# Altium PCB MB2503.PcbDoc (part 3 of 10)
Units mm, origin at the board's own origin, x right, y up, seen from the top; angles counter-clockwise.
Board outline 127 x 97 mm, 6 copper layers (Top Layer, Signal Layer 1, Signal Layer 2, Signal Layer 3, Signal Layer 4, Bottom Layer), stack 1.557 mm thick; 572 components, 468 nets, 2377 pads, 1704 vias.
Unrouted connection lines stored in the file: 3.
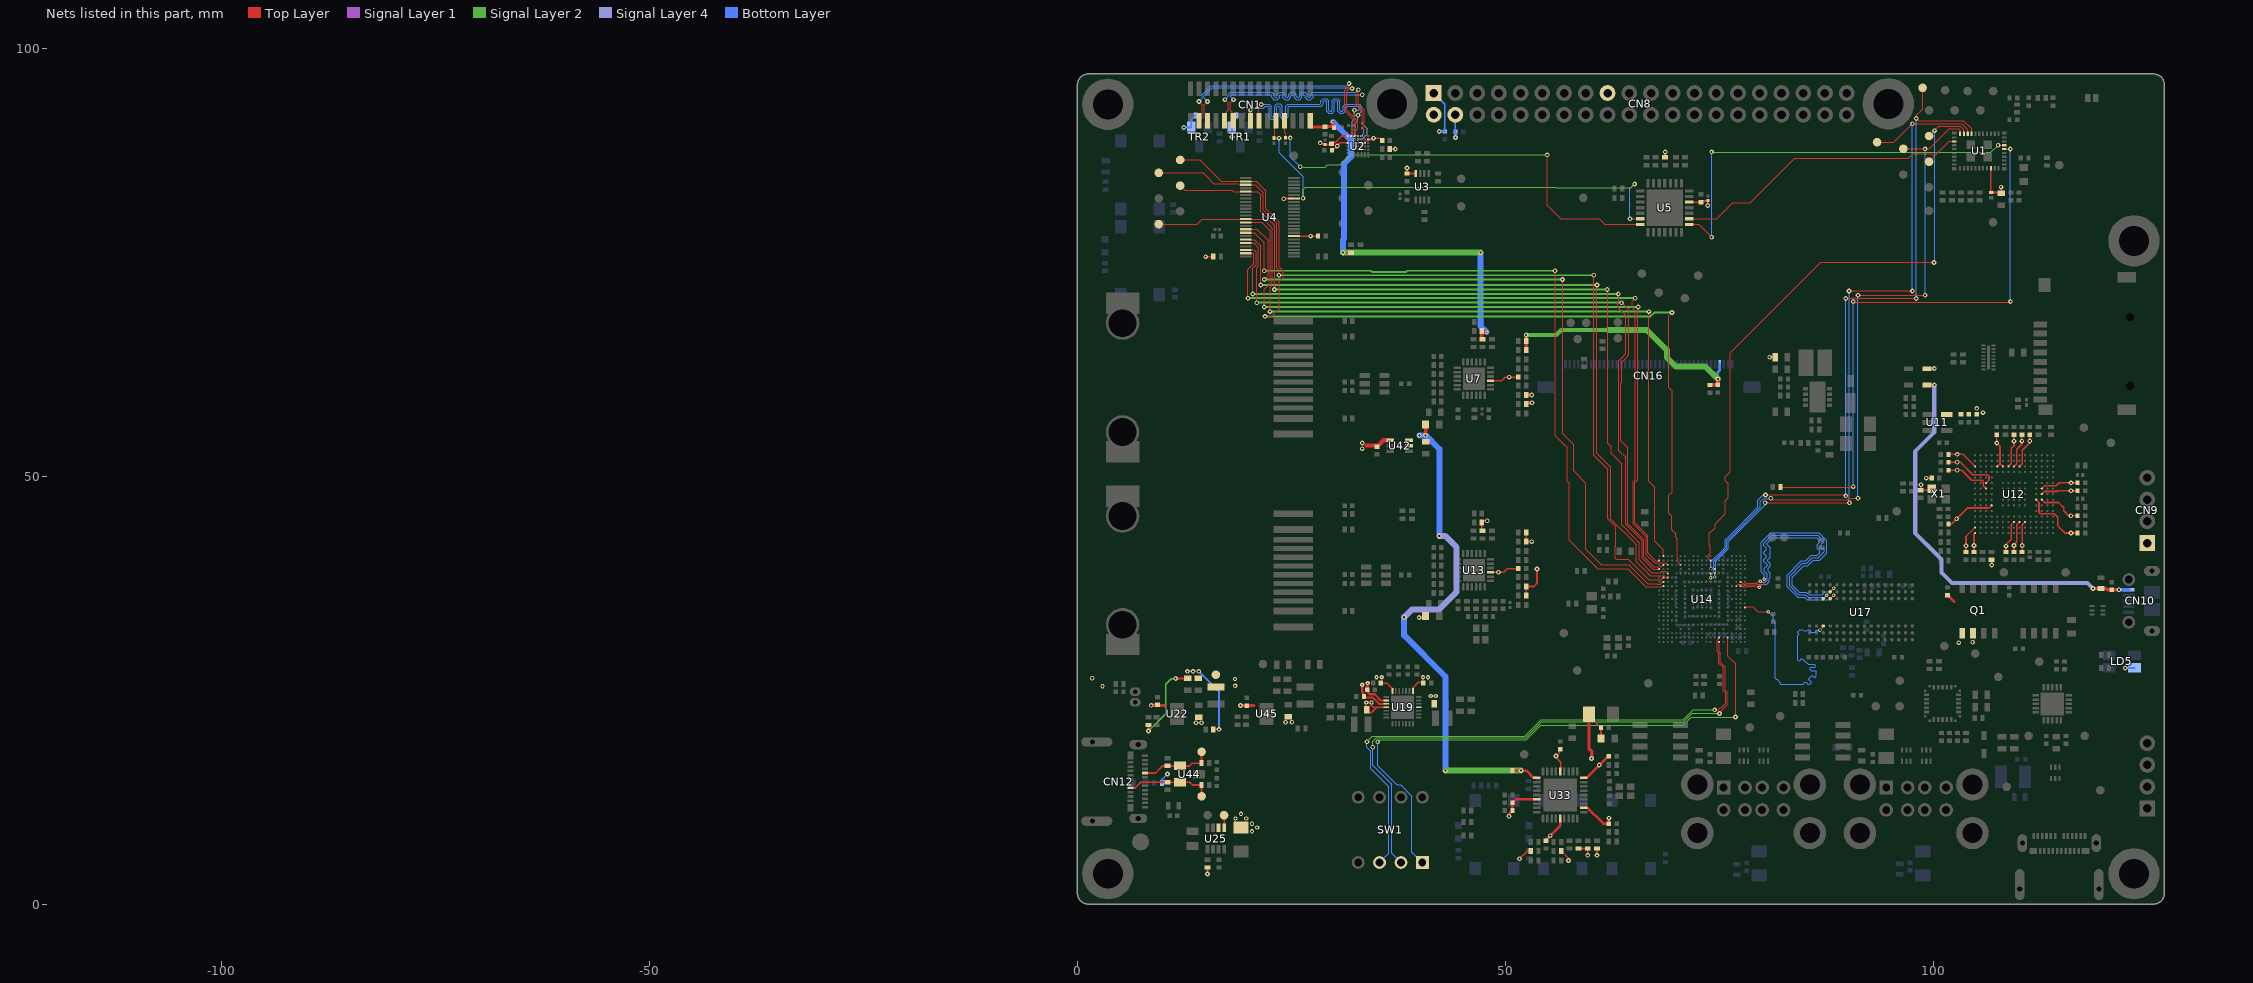
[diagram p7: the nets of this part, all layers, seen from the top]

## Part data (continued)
CN9 CN13: library part MCD-00029, "Header, 4x1, 2.54mm, VR, TH, T=5.84mm/2.54mm", Manufacturer=SAMTEC, Manufacturer_Part_Number=TSW-104-07-G-S
CN10: library part MCD-00028, "MicroUSB_TypeB, 5pins, 0.65mm, RA, SMD, T=2.9mm", Manufacturer=MOLEX, Manufacturer_Part_Number=1050170001
CN11: library part MCD-00655, "Header, 2x1, 1.25mm, VR, TH, T=2.25mm/2.3mm", Manufacturer=MOLEX, Manufacturer_Part_Number=53047-0210
CN16: library part MCD-02589, "Socket_FFC/FPC, 40pins, 0.5mm, RA, SMD, T=1.9mm", Manufacturer=MOLEX
D1 D3 D4: library part MCD-00034, Manufacturer=STMICROELECTRONICS, Manufacturer_HQ_COO=EU, Package=SOD-323
D2: library part MCD-00033, "Low Drop power Schottky rectifier(1A, 40V, 0.4V)", Manufacturer=STMICROELECTRONICS, Manufacturer_HQ_COO=EU, Package=DO216-AA
HW2: library part MCD-00235, "Sticker Board 25x9 mm", Manufacturer=N/A
HW3: library part MCD-00547, "Sticker product 25x9 mm", Manufacturer=N/A, Manufacturer_HQ_COO=Unknown
L1: library part MCD-00657, "Inductor, 2.4nH, +/-0.2nH, Itemp=850mA, 50R, 0402, T=0.6mm, Qmin=20", Manufacturer=MURATA, Manufacturer_Part_Number=LQW15AN2N4C00#, Package=0402
L2: library part MCD-00659, "Inductor, 2.2uH, +/-20%, 1050mA, 0R2, 0603, T=1mm", Manufacturer=MURATA, Manufacturer_Part_Number=LQM18PN2R2MGH, Package=0603
L3: library part MCD-00048, "Inductor, 4.7uH, +/-30%, 1A, 180mR, 1210, T=1.7mm", Manufacturer=MURATA, Manufacturer_Part_Number=LQH32PN4R7NN0L, Package=1210
L4 L5: library part MCD-00047, "Ferrite bead, 600R @1 00MHz, +/-25%, 350mA, 0R5, 0603, T=0.8mm", Manufacturer=TAI-TECH, Manufacturer_Part_Number=FCM1608KF-601T03, Package=0603
L6 L8: library part MCD-00161, "Inductor, 2.2uH, +/-20%, 2,2A, 84mR, 1008, T=1.2mm", Manufacturer=TOKO, Manufacturer_Part_Number=DFE252012P-2R2M{}P2, Package=1008
L9 L11: library part MCD-04058, "Inductor, 1uH, +/-20%, 3.6A, 57mR, 0806, T=1mm", Manufacturer="SAMSUNG ELECTRO-MECHANICS", Manufacturer_Part_Number=CIGT201610LH1R0MNE, Package=0806
L12: library part MCD-00305, "Ferrite bead, 26R @ 100Mhz, +/-25%, 6000mA, 0R007, 0603, T=0.75mm", Manufacturer=MURATA, Manufacturer_Part_Number=BLM18KG260TN1, Package=0603
LD1: library part MCD-00050, "LED, Green, 2V, 20mA, 0603", Manufacturer=EVERLIGHT, Manufacturer_Part_Number=19-213SYGC/S530-E2/TR8, Package=0603
LD2 LD4: library part MCD-00049, "LED, Red, 0603", Manufacturer=EVERLIGHT, Manufacturer_Part_Number=19-213/R6C-AP1Q2B/3T, Package=0603
LD3: library part MCD-01131, "LED Blue, 0603 SMD, Forward Voltage Min=2,8V, Max=3,1V", Manufacturer=EVERLIGHT, Manufacturer_Part_Number=19-217/BHC-ZL1M2RY/3T, Package=0603
LD5: library part MCD-02629, "LED Bicolor, Green, Red, 4-PLCC", Manufacturer="VISUAL COMMUNICATIONS COMPANY", Manufacturer_Part_Number=CMD6722VRVGCTR8, Package=4-PLCC
LD6: library part MCD-00321, "LED, Orange, 0603", Manufacturer=EVERLIGHT, Manufacturer_Part_Number=19-217/S2C-AM2N2VY/3T, Package=0603
LD7: library part MCD-00050, "LED, Green, 0603", Manufacturer=EVERLIGHT, Manufacturer_Part_Number=19-213SYGC/S530-E2/TR8, Package=0603
Q1 Q2: library part MCD-02152, "MOSFET, Dual N-channel 30 V, 0.016 Ω typ., 40 A, STripFET™ H5 Power MOSFET", Manufacturer=STMICROELECTRONICS, Manufacturer_HQ_COO=EU, Package=PowerFLAT-8
R1 R2 R10 R11 R12 R19 R20 R21 R28 R30 R45 R54 R55 R56 R57 R60 R61 R64 R68 R77 R81 R85 R88 R90 R91 R96 R103 R104 R105 R106 R133 R166 R167 R188 R189 R190 R191 R192: library part MCD-00052, "Resistor, 0R, 0402, +/-5%, 1/16W", Manufacturer=YAGEO, Manufacturer_Part_Number=RC0402JR-070RL, Package=0402
R3 R4 R5 R6 R7 R8 R9 R22 R23 R24 R25 R26 R29 R32 R33 R34 R38 R43 R48 R65 R69 R70 R72 R73 R78 R83 R84 R93 R100 R102 R141 R162 R163 R176 R178 R180 R187: library part MCD-00053, "Resistor, 10K, 0402, +/-1%, 1/16W", Manufacturer=YAGEO, Manufacturer_Part_Number=RC0402FR-0710KL, Package=0402
R13 R53 R58 R59 R87 R89 R94: library part MCD-00065, "Resistor, 4K7, 0402, +/-1%, 1/16W", Manufacturer=YAGEO, Manufacturer_Part_Number=RC0402FR-074K7L, Package=0402
R14 R15 R16 R17 R18 R144 R149: library part MCD-00063, "Resistor, 47K, 0402, +/-1%, 1/16W", Manufacturer=YAGEO, Manufacturer_Part_Number=RC0402FR-0747KL, Package=0402
R27 R52 R76 R110: library part MCD-00441, "Resistor, 270R, 0402, +/-1%, 1/16W", Manufacturer=YAGEO, Manufacturer_Part_Number=RC0402FR-07270RL, Package=0402
R31 R71 R75 R80 R82 R108 R120 R121 R168 R169: library part MCD-00068, "Resistor, 1K5, 0402, +/-1%, 1/16W", Manufacturer=YAGEO, Manufacturer_Part_Number=RC0402FR-071K5L, Package=0402
R35 R115 R116: library part MCD-00181, "Resistor, 0R, 0603, +/- 0.5mR, 1/4W", Manufacturer="ROHM SEMICONDUCTOR", Manufacturer_Part_Number=PMR03EZPJ000, Package=0603
R36 R41 R51 R79 R86 R98 R109: library part MCD-00455, "Resistor, 33R, 0402, +/-1%, 1/16W", Manufacturer=YAGEO, Manufacturer_Part_Number=RC0402FR-0733RL, Package=0402
R37 R39 R40 R42 R92 R95 R97 R99: library part MCD-00565, "Resistor, 49R9, 0402, +/-1%, 1/16W", Manufacturer=YAGEO, Manufacturer_Part_Number=RC0402FR-0749R9L, Package=0402
R44 R46 R156 R158 R159 R160 R161 R164 R165: library part MCD-00059, "Resistor, 100K, 0402, +/-1%, 1/16W", Manufacturer=YAGEO, Manufacturer_Part_Number=RC0402FR-07100KL, Package=0402
R47 R101: library part MCD-00723, "Resistor, 12K1, 0402, +/-1%, 1/16W", Manufacturer=YAGEO, Manufacturer_Part_Number=RC0402FR-0712K1L, Package=0402
R49: library part MCD-00060, "Resistor, 10R, 0603, +/-1%, 1/4W", Manufacturer="ROHM SEMICONDUCTOR", Manufacturer_Part_Number=ESR03EZPF10R0, Package=0603
R50 R107: library part MCD-00189, "Resistor, 22R, 0402, +/-1%, 1/16W", Manufacturer=YAGEO, Manufacturer_Part_Number=RC0402FR-0722RL, Package=0402
R62 R63: library part MCD-00433, "Resistor, 2K4, 0402, +/-1%, 1/16W", Manufacturer=YAGEO, Manufacturer_Part_Number=RC0402FR-072K4L, Package=0402
R66 R128: library part MCD-00185, "Resistor, 3K, 0402, +/-1%, 1/16W", Manufacturer=YAGEO, Manufacturer_Part_Number=RC0402FR-073KL, Package=0402
R67 R186: library part MCD-00489, "Resistor, 560R, 0402, +/-1%, 1/16W", Manufacturer=YAGEO, Manufacturer_Part_Number=RC0402FR-07560RL, Package=0402
R74 R173 R175 R177 R182: library part MCD-00067, "Resistor, 100R, 0402, +/- 1%, 1/16W", Manufacturer=YAGEO, Manufacturer_Part_Number=RC0402FR-07100RL, Package=0402
R111: library part MCD-03129, "Resistor, 12mR, 0603, +/-1%, 1/2W", Manufacturer=VISHAY, Manufacturer_Part_Number=WFCP0603R0120FE66, Package=0603
R112 R179: library part MCD-00120, "Resistor, 240R, 0402, +/-1%, 1/16W", Manufacturer=YAGEO, Manufacturer_Part_Number=RC0402FR-07240RL, Package=0402
R113: library part MCD-00165, "Resistor, 150K, 0402, +/-1%, 1/16W", Manufacturer=YAGEO, Manufacturer_Part_Number=RC0402FR-07150KL, Package=0402
R114: library part MCD-00166, "Resistor, 120K, 0402, +/-1%, 1/16W", Manufacturer=YAGEO, Manufacturer_Part_Number=RC0402FR-07120KL, Package=0402
R117 R125 R152 R183: library part MCD-00062, "Resistor, 330R, 0402, +/-1%, 1/16W", Manufacturer=YAGEO, Manufacturer_Part_Number=RC0402FR-07330RL, Package=0402
R129: library part MCD-00384, "Resistor, 13K, 0603,+/-1%, 1/10W", Manufacturer=YAGEO, Manufacturer_Part_Number=RC0603FR-0713KL, Package=0603
R134: library part MCD-00420, "Resistor, 2K ,0603, +/-1%, 1/10W", Manufacturer=YAGEO, Manufacturer_Part_Number=RC0603FR-072KL, Package=0603
R135: library part MCD-00521, "Resistor, 75K, 0402, +/-1%, 1/16W", Manufacturer=YAGEO, Manufacturer_Part_Number=RC0402FR-0775KL, Package=0402
R136: library part MCD-00435, "Resistor, 24K, 0402, +/-1%, 1/16W", Manufacturer=YAGEO, Manufacturer_Part_Number=RC0402FR-0724KL, Package=0402
R142: library part MCD-00259, "Resistor, 33K, 0603, +/-1%, 1/10W", Manufacturer=YAGEO, Manufacturer_Part_Number=RC0603FR-0733KL, Package=0603
R143: library part MCD-00530, "Resistor, 8K2, 0603, +/-1%, 1/10W", Manufacturer=YAGEO, Manufacturer_Part_Number=RC0603FR-078K2L, Package=0603
R145 R147: library part MCD-00333, "Resistor, 5K1, 0402, +/-1%, 1/16W", Manufacturer=YAGEO, Manufacturer_Part_Number=RC0402FR-075K1L, Package=0402
R146: library part MCD-00187, "Resistor, 12K, 0402, +/-1%, 1/16W", Manufacturer=YAGEO, Manufacturer_Part_Number=RC0402FR-0712KL, Package=0402
R153 R154 R155 R157 R170 R171 R174 R181 R198 R200 R207 R209 R214 R215: library part MCD-00061, "Resistor, 1K, 0402, +/-1%,1/16W", Manufacturer=YAGEO, Manufacturer_Part_Number=RC0402FR-071KL, Package=0402
R172 R184: library part MCD-00507, "Resistor, 680R, 0402, +/-1%, 1/16W", Manufacturer=YAGEO, Manufacturer_Part_Number=RC0402FR-07680RL, Package=0402
R185: library part MCD-00481, "Resistor, 47R, 0402, +/-1%, 1/16W", Manufacturer=YAGEO, Manufacturer_Part_Number=RC0402FR-0747RL, Package=0402
SW1: library part MCD-02256, "Quad SPST switch, TH, 2.54mm pitch, height 7.5mm", Manufacturer=ECE, Package=9.65x12.2mm
TP1 TP2 TP3 TP4 TP5 TP6 TP7 TP8 TP9 TP10 TP11 TP12 TP13 TP14 TP15 TP16 TP17 TP18 TP19 TP20 TP21 TP22 TP23 TP24 TP25 TP26 TP27 TP28 TP29 TP30 TP31 TP32 TP33 TP34 TP35 TP36 TP37 TP38 TP39 TP40 TP41 TP42 TP43 TP44 TP45 TP46 TP47 TP48 TP50 TP51 TP52 TP53 TP54 TP55 TP56 TP57 TP58 TP59 TP61 TP63 TP64 TP65 TP74 TP75: library part MCD-00074, "Test Point 1mm", Manufacturer=N/A, Manufacturer_HQ_COO=Unknown
TP49 TP62 TP67 TP68 TP73 TP77: library part MCD-00074, "Test Point, SMD, 1mm", Manufacturer=N/A, Manufacturer_HQ_COO=Unknown
TP76: library part MCD-00177, "Test Point, SMD, 2mm", Manufacturer=N/A
TR1 TR2: library part MCD-02156, "MOSFET, N-Channel , Vds: 25V, Id: 0,22A, Vgs(th): 1.06V, Vgs(max): +/-8V, Rdson:5ohm@Vgs=2.7V, Qg=0,49nC", Manufacturer="ON SEMICONDUCTOR", Manufacturer_Part_Number=FDV301N, Package=SOT23-3
U1: library part MCD-00268, "IEEE802.11b/g/n W-LAN + Bluetooth 4.1+EDR module", Manufacturer=MURATA, Manufacturer_Part_Number=LBEE5KL1DX-977, Package=6.95x5.15x1.1mm
U2: library part MCD-02213, "Dual mode MIPI CSI-2 / SMIA CCP2 de-serializer", Manufacturer=STMICROELECTRONICS, Manufacturer_HQ_COO=EU, Manufacturer_Part_Number=STMIPID02/TR, Package=VFBGA-49
U3: library part MCD-00264, "Dual bit dual supply bus transceiver", Manufacturer="TEXAS INSTRUMENTS", Package=VSSOP-8
U4: library part MCD-02226, "16-bit translating transceiver", Manufacturer="TEXAS INSTRUMENTS", Package=TVSOP-56
U5: library part MCD-02210, "16-bit port expander with I2C control", Manufacturer=MICROCHIP, Manufacturer_Part_Number=MCP23017T-E/ML, Package=QFN-28
U6: library part MCD-00249, "ESD protection for SD card 2.0", Manufacturer=STMICROELECTRONICS, Manufacturer_HQ_COO=EU, Package=uQFN-16
U7 U13: library part MCD-00719, "10/100M RMII Ethernet transceiver", Manufacturer=MICROCHIP, Package=VQFN-24
U8 U15: library part MCD-00250, "Very low capacitance ESD protection , 4 lines", Manufacturer=STMICROELECTRONICS, Manufacturer_HQ_COO=EU, Package=SOT23-6
U9: library part MCD-00082, "White LED power supply for large display backlight, QFN8", Manufacturer=STMICROELECTRONICS, Manufacturer_HQ_COO=EU, Package=QFN-8
U10 U37 U40 U41: library part MCD-00170, "ESD protection 6V1", Manufacturer=STMICROELECTRONICS, Manufacturer_HQ_COO=EU, Manufacturer_Part_Number=ESDALC6V1-1U2, Package=ST0201
U11: library part MCD-00086, "Ultra low drop-low noise BiCMOS voltage, regulators low ESR capacitors compatible", Manufacturer=STMICROELECTRONICS, Manufacturer_HQ_COO=EU, Package=SOT23-5
U12: library part MCD-01523, "MCU, Arm Cortex-M7 32-bit MCU, 512KB Flash, 276KB RAM, With Crypto", Manufacturer=STMICROELECTRONICS, Manufacturer_HQ_COO=EU, Manufacturer_Part_Number=STM32F723IEK6, Package=UFBGA176+25
U14: library part MCD-02251, "Cortex-A7 @ 900MHz, 128KB-ROM, 128KB-SRAM, 2x Ethernet, 2x ADC, 2x CAN FD, TSC, Camera, Display, Secure Boot, Cryptography, DRAM enc/dec, PKA", Manufacturer=STMICROELECTRONICS, Manufacturer_HQ_COO=EU, Package=TFBGA-320
U16: library part MCD-00251, "High power transient voltage suppressor, 7V breakdown", Manufacturer=STMICROELECTRONICS, Manufacturer_HQ_COO=EU, Manufacturer_Part_Number=ESDA7P60-1U1M, Package=QFN1610
U17: library part MCD-01811, "Memory,DDR3L,4Gb,256Mbx16,933Mhz,1V35,TFBGA", Manufacturer=NANYA, Package=VFBGA-96
U18 U26 U27 U28 U29 U32: library part MCD-00649, "Common mode filter with ESD protection for USB 2.0 interface", Manufacturer=STMICROELECTRONICS, Manufacturer_HQ_COO=EU, Package=QFN-6
U19: library part MCD-04949, "Power Management IC for STM32MP13xD/F series (overdrive) with 2 step-down SMPS, 4 LDOs, 2 GPOs, WFQFN 28L (4.0 x 4.0 x 1.0 mm)", Manufacturer=STMICROELECTRONICS, Manufacturer_Part_Number=STPMIC1LDPQR, Package="VFQFPN-28 4x4mm"
U20: library part MCD-02130, "USB Type-C Port Protection for USB DRP Power Delivery, PPS compliant", Manufacturer=STMICROELECTRONICS, Manufacturer_HQ_COO=EU, Package=QFN-20
U21: library part MCD-02218, "Arm Cortex-M0+ 32-bit MCU, up to 128 KB Flash, 36 KB RAM,  4x USART, timers, ADC, DAC, comm. I/Fs, 1.7-3.6V", Manufacturer=STMICROELECTRONICS, Manufacturer_HQ_COO=EU, Package=UFQFPN28
U22 U45: library part MCD-02243, "Regulator, 3A, DC step-down switching", Manufacturer=STMICROELECTRONICS, Manufacturer_HQ_COO=EU, Package=VFDFPN-8
U23 U24: library part MCD-00123, "IC,Dual-Channel-Power-Switch,500mA,100mR,SO8", Manufacturer=STMICROELECTRONICS, Manufacturer_HQ_COO=EU, Package=SO-8
U25: library part MCD-03955, "IC, Electronic fuse for 5V line, Vclamp 5V7, Vin max 25V", Manufacturer=STMICROELECTRONICS, Package=TSOT23-8L
U30 U31 U38 U39: library part MCD-01026, "High power transient voltage suppressor", Manufacturer=STMICROELECTRONICS, Manufacturer_HQ_COO=EU, Manufacturer_Part_Number=ESDA7P120-1U1M, Package=QFN1610
U33: library part MCD-00145, "USB HUB 2,0 Controller", Manufacturer=MICROCHIP, Package=QFN-36
U34: library part MCD-01207, "Diode, ESD TVS, 22V, 200nA, 25V8, QFN1610", Manufacturer=STMICROELECTRONICS, Manufacturer_HQ_COO=EU, Manufacturer_Part_Number=ESDA25P35-1U1M, Package=QFN1610
U35: library part MCD-02422, "LCD,  TFT, 4.3 inch, 480x272 pixels with LED Backlight and Capacitive touch panel, high luminance with 0.5mm pitch flat cable", Manufacturer=ROCKTECH, Package=67.2x105.5x4.53mm
U36: library part MCD-01207, "High power Transient voltage suppressor:25V/35A EOS and ESD transients protection.", Manufacturer=STMICROELECTRONICS, Manufacturer_HQ_COO=EU, Manufacturer_Part_Number=ESDA25P35-1U1M, Package=QFN1610
U42: library part MCD-02311, "IC, 5V5, 1.5A, 90mR Self-Protected load switch with controlled rise time", Manufacturer="TEXAS INSTRUMENTS", Manufacturer_Part_Number=TPS22919DCKR, Package=SC70-6
U44: library part MCD-01125, "Diode, ESD Transil, 24V, 1uA, 30V, SOT23-3", Manufacturer=STMICROELECTRONICS, Manufacturer_HQ_COO=EU, Package=SOT23-3
X1: library part MCD-00597, "Oscillator, SPXO, 25Mhz, +/-50ppm, 3V3, square wave, 2.5x2mm", Manufacturer=NDK, Manufacturer_Part_Number=NZ2520SH-25MHZ-END4869C, Package=2.5x2.0mm
X2: library part MCD-01479, "Crystal, 32.768kHz, 6pF, +/-20ppm, 80K, 2.05x1.2mm", Manufacturer=NDK, Manufacturer_Part_Number=NX2012SA-32.768KHZ-EXS00A-MU00527, Package=2.05x1.2mm
X3: library part MCD-01364, "Crystal, 25MHz, 6pF, +/-20ppm, 80R, 2x1.6mm", Manufacturer=NDK, Manufacturer_Part_Number=NX2016SA-25MHZ-EXS00A-CS11321, Package=2.0x1.6mm
X4 X5: library part MCD-01036, "Crystal, 24MHz, 6pF, +/-20ppm, 80R, 2x1.6mm", Manufacturer=NDK, Manufacturer_Part_Number=NX2016SA-24MHZ-EXS00A-CS10820, Package=2.0x1.6mm

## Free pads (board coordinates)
  round 6 hole 3.5: 1(3.55,3.55) 1(3.55,93.45) 1(36.75,93.5) 1(94.75,93.5) 1(123.45,3.55) 1(123.45,77.5)

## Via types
v1: diameter 0.55, hole 0.25, Top Layer to Bottom Layer, 1335 vias
v2: diameter 0.4, hole 0.2, Top Layer to Bottom Layer, 262 vias
v3: diameter 0.5, hole 0.2, Top Layer to Bottom Layer, 51 vias
v4: diameter 0.26, hole 0.1, Top Layer to Signal Layer 1, tented both sides, 29 vias
v5: diameter 0.5, hole 0.25, Top Layer to Bottom Layer, 18 vias
v6: diameter 0.4, hole 0.2, Top Layer to Bottom Layer, tented both sides, 9 vias

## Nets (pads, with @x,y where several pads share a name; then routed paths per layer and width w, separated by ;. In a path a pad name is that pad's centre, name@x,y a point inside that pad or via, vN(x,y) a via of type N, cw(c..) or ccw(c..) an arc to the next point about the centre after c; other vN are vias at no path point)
1V8_PERIPH: C9.2 C10.2 C11.2 C12.2 C13.2 C26.2 C99.2 R5.1 R22.2 R168.2 R169.2 TR1.1 TR2.1 U2.A2 U2.B3 U2.C3 U2.C4 U2.G1 U2.G3 U3.8 U4.31 U4.42 U19.23 | length 25
  Top Layer w0.1: U2.B3@33.575,88.95 U2.A2@33.975,89.35
  Top Layer w0.2: v1(14.975,75.65) R22.2@15.875,75.65 ; v1(24.1,82.425) 24.125,82.45 U4.42@25.3,82.45 ; U4.31@25.3,78.05 C26.2@28.1,78.05 ; v1(28.375,88.95) 28.47,88.95 28.6,88.82 28.875,88.82 C10.2@28.95,88.745 29.595,88.745 C9.2@29.7,88.85 ; C9.2@29.7,88.95 29.742,88.992 30.117,88.992 30.875,89.75 U2.G1@31.575,89.75 ; C12.2@29.75,88.075 29.85,88.075 30.725,88.95 U2.G3@31.575,88.95 ; U2.C4@33.175,88.55 U2.C3@33.175,88.95 U2.B3@33.575,88.95 ; U2.A2@33.975,89.35 34.45,89.35 v1(34.6,89.5) 35.325,89.5 C11.2@35.6,89.225 ; 35.45,23.8 U19.23@36.1,23.8 ; R5.1@36.5,88.225 v1(37.15,88.225) ; v1(38.5,86) 38.5,85.38 C13.2@38.515,85.365 U3.8@39.54,85.365
  Top Layer w0.25: 34.73,24.52 35.45,23.8
  Top Layer w0.3: C99.2@33.85,25.05 33.888,25.087 33.888,25.788 v3(33.925,25.825) ; C99.2@33.955,24.945 33.955,24.764 33.975,24.744 33.975,24.713 34.168,24.52 34.73,24.52
  Bottom Layer w0.2: v1(12.425,90.75) TR2.1@13.3,90.75 13.3,91.65 R169.2@13.8,92.15 ; v1(18.05,89.625) TR1.1@18.05,90.75 18.05,91.65 R168.2@18.55,92.15
  other v1: 27.25,78.05 30.35,88.575
  other v5: 2.925,25.45 18.425,25.5 18.4,26.3 1.725,26.4
3V3_AO: C7.1 C18.2 C19.2 C22.2 C23.2 C79.2 C101.2 C113.2 C114.2 CN8.1 CN8.17 L5.2 L8.2 R9.1 R73.2 R78.2 R80.2 R83.2 R100.2 R102.2 R135.2 R186.2 TP62.1 U1.30 U5.5 U13.9 U42.1 | length 46.9
  Top Layer w0.2: R135.2@8.275,20.925 8.3,20.9 v1@8.3,20.25 ; v1@11.5,26.375 C113.2@12.875,26.375 ; R186.2@15.9,20.5 15.975,20.425 v1(16.55,20.425) ; v1(39.925,33.5) 40.5,33.5 L5.2@40.675,33.675 ; R78.2@47.35,43.625 47.25,43.725 R73.2@47.25,44.575 47.475,44.8 v1(47.875,44.8) ; U13.9@48.275,38.775 49.8,38.775 50.225,39.2 C79.2@51.525,39.2 ; R102.2@52.425,36.05 R100.2@52.425,37.125 53.35,37.125 53.7,37.475 v1(53.7,39.15) ; R80.2@52.425,43.425 R83.2@52.425,42.35 v1(53.075,42.35) ; R9.1@68.625,87.25 68.675,87.3 v1(68.675,87.875) ; U5.5@71.475,82.025 C22.2@72.85,82.025 72.975,82.15 73.6,82.15 C23.2@73.65,82.2 v1(73.65,81.625) ; U1.30@106.725,85.975 106.725,83.2 C18.2@106.775,83.15 107.85,83.15 C19.2@107.925,83.075 v1(107.925,83.775)
  Top Layer w0.5: 33.775,53.575 34.85,53.575 34.97,53.455 C101.2@35,53.455 ; C101.2@35,53.45 35.025,53.45 35.03,53.455 35.03,53.48 35.75,54.2 U42.1@36.35,54.2
  Signal Layer 2 w0.2: v1(8.3,20.225) 10.325,22.25 10.325,25.7 10.975,26.35 11.4,26.35 v1@11.45,26.4
  Bottom Layer w0.2: v1(14.175,27.2) 16.55,24.825 v1(16.55,20.425) ; CN8.1@41.62,94.77 42.925,93.465 C7.1@42.925,90.275 v1(42.275,90.275)
  other v1: 11.475,26.375 12.85,27.2 13.513,27.2 49.2,38.775 33.275,53.225 33.275,53.887
3V3_STLK: C42.2 C43.2 C44.2 C46.2 C47.2 C48.2 C49.2 C57.2 C58.2 C59.2 C61.2 C62.2 C63.2 C67.2 C68.2 C69.2 C74.2 C75.2 C76.2 C77.2 C78.2 CN9.1 LD5.3 R65.1 R89.1 U11.5 U12.C1 U12.C5 U12.C6 U12.C7 U12.C8 U12.C9 U12.F3 U12.G3 U12.G13 U12.H13 U12.J12 U12.J13 U12.K4 U12.N8 U12.N9 U12.N10 U12.P1 U12.R1 X1.4 | length 81.1
  Top Layer w0.2: v1(98.575,49) 98.575,48.425 R65.1@98.525,48.375 99.625,48.375 X1.4@99.8,48.55 ; v1(99.175,49.775) C61.2@99.8,49.775 ; C68.2@101.775,44.4 102.1,44.4 v1(102.725,45.025) 103.975,46.275 106.5,46.275 U12.K4@106.825,46.6 ; C59.2@101.775,50.7 v1(102.8,50.7) 103.325,50.7 104.5,49.525 105.7,49.525 105.85,49.375 105.85,48.875 U12.G3@106.175,48.55 ; C58.2@101.775,51.625 v1(102.8,51.625) 103.175,51.625 104.625,50.175 106.31,50.175 106.5,49.985 106.5,49.525 U12.F3@106.175,49.2 ; C57.2@101.775,52.55 v1(102.8,52.55) 103.475,52.55 U12.C1@104.875,51.15 ; C74.2@103.825,41.15 v1(103.825,41.875) 103.825,42.95 U12.P1@104.875,44 ; C75.2@104.75,41.15 v1(104.75,41.9) 104.75,43.225 U12.R1@104.875,43.35 ; v1(106.825,39.625) R89.1@106.825,40.25 ; C46.2@107.425,54.85 v1(107.425,53.889) 107.8,53.514 107.8,51.475 ; U12.C5@107.475,51.15 107.8,51.475 ; U12.C6@108.125,51.15 107.8,51.475 ; C76.2@108.5,41.15 v1(108.5,41.825) 108.5,42.05 109.1,42.65 109.1,44.325 U12.N8@109.425,44.65 ; U12.C7@108.775,51.15 109.1,51.475 109.1,53.25 109.425,53.575 v1(109.425,54.1) C47.2@109.425,54.85 ; C77.2@109.425,41.15 v1(109.425,41.9) 109.425,42.025 109.75,42.35 109.75,44.325 U12.N9@110.075,44.65 ; U12.C8@109.425,51.15 109.75,51.475 109.75,53.15 110.35,53.75 v1(110.35,54.1) C48.2@110.35,54.85 ; U12.C9@110.075,51.15 110.4,51.475 110.4,53.025 111.275,53.9 C49.2@111.275,54.85 ; C78.2@110.35,41.15 110.4,41.2 v1(110.4,41.9) 110.4,44.325 U12.N10@110.725,44.65 ; U12.J12@112.025,47.25 112.35,46.925 112.35,45.775 112.5,45.625 114.15,45.625 114.55,45.225 114.55,44.175 115.35,43.375 v1(116.1,43.375) C69.2@116.85,43.375 ; U12.J13@112.675,47.25 113,46.925 114.625,46.925 115.25,46.3 115.25,45.95 115.825,45.375 v1(116.075,45.375) C67.2@116.85,45.375 ; U12.H13@112.675,47.9 113,48.225 114.4,48.225 114.475,48.3 v1(116.1,48.3) C63.2@116.85,48.3 ; U12.G13@112.675,48.55 113,48.875 114.35,48.875 114.7,49.225 v1(116.1,49.225) C62.2@116.85,49.225
  Bottom Layer w0.2: v1(122.425,27.6) LD5.3@123.525,27.6
  other v1: 111.275,54.125 105.8,57.425 105.075,57.925
3V3_SW: C6.2 C30.2 C50.1 C53.2 C115.2 C117.2 C150.2 C154.2 C157.2 C165.2 C168.2 C169.2 C170.2 CN1.15 CN16.4 L4.2 R20.2 R26.2 R29.2 R31.2 R32.2 R43.2 R48.2 R161.2 R162.1 R163.2 R164.2 R165.2 U7.9 U33.5 U33.10 U33.15 U33.23 U33.29 U33.36 U42.5 U42.6 | length 173.7
  Top Layer w0.2: v1(31.025,76.125) R20.2@31.975,76.125 ; U7.9@48.275,61.15 49.55,61.15 49.975,61.575 v1(50.45,61.575) C30.2@51.525,61.575 ; v1(51.65,5.3) 52.537,6.187 52.962,6.187 R164.2@52.975,6.2 ; U33.5@56.4,15.5 56.475,15.575 56.475,16.597 55.925,17.147 v1(55.925,17.3) 56.287,17.662 56.287,17.987 C150.2@56.4,18.1 ; R165.2@56.525,6.2 56.55,6.2 57.382,5.368 v1(57.382,5.089) ; R161.2@58.55,6.5 R162.1@59.625,6.5 v1(59.625,5.7) ; v1(60.7,5.7) R163.2@60.7,6.5
  Top Layer w0.3: v1(50.425,10.275) 50.425,10.525 C168.2@50.825,10.925 C165.2@50.825,11.85 51.225,12.25 U33.15@53.65,12.25 ; C157.2@50.825,15.6 52.45,15.6 53.3,14.75 U33.10@53.65,14.75 ; C170.2@54.75,7.4 54.75,7.5 v1(55.25,8) 56.4,9.15 U33.23@56.4,10 ; U33.29@59.15,11.25 59.611,11.25 61.461,9.4 C169.2@62.1,9.4 v1(62.1,10.05) ; U33.36@59.15,14.75 59.475,14.75 v1(60.975,16.25) ; v1@61.075,16.25 v1(60.975,16.25) ; C154.2@62.1,17.275 62,17.275 v1(60.975,16.25)
  Top Layer w0.4: CN1.15@27.2,91.525 27.2,90.905 27.3,90.805 28.88,90.805 C117.2@28.925,90.85 28.939,90.864 29.805,90.864 29.864,90.805 29.92,90.805 29.975,90.75 C6.2@29.975,90.725 ; C6.2@29.85,90.95 v2(29.85,91.4) ; v1(40.675,54.775) L4.2@40.675,56.025 ; R29.2@47.35,66 47.25,66.1 R26.2@47.25,66.95 47.375,66.825 v2(47.825,66.825) ; R48.2@52.425,58.425 52.575,58.575 v1(53.1,58.575) ; R43.2@52.425,59.5 v1(53.075,59.5) ; R32.2@52.425,64.725 R31.2@52.425,65.8 v1(52.425,66.5) ; C50.1@73.905,60.675 74.83,60.675 74.825,60.68 v1(74.825,61.374)
  Signal Layer 2 w0.5: v1(52.425,66.5) 55.95,66.5 56.525,67.075 62,67.075
  Signal Layer 2 w0.7: v1(31.025,76.125) 32.717,76.125 v1(47.1,76.125) 44.473,76.125 ; v1(43,15.6) 43.002,15.598 v1(51.835,15.598) ; 62,67.075 66.55,67.075 68.875,64.75 68.875,63.875 69.925,62.825 73.374,62.825 v1(74.825,61.374)
  Signal Layer 4 w0.7: v1(38.175,33.525) 39.1,34.45 42.275,34.45 44.311,36.486 44.311,41.689 42.975,43.025 v1(42.275,43.025)
  Bottom Layer w0.3: v1(74.825,61.374) 74.825,62.171 75.025,62.371 CN16.4@75.025,63.1
  Bottom Layer w0.7: v2(29.85,91.4) 30.5,90.75 31.95,89.3 31.95,87.325 31.15,86.525 31.15,77.75 31.025,77.625 v1(31.025,76.125) ; v1(38.175,33.525) 38.175,31.4 43,26.575 v1(43,15.6) ; v1(39.95,54.775) v1(40.675,54.775) 42.275,53.175 v1(42.275,43.025) ; v1(47.1,76.125) 47.1,67.55 v2@47.779,66.871
5V_USB_CHGR: C84.2 CN10.1 D3.1 U16.1 | length 47.7
  Top Layer w0.3: D3.1@99.245,60.65 v1(100.125,60.65)
  Top Layer w0.4: v1(118.65,36.875) U16.1@119.575,36.875 120.2,36.875 120.35,36.725 C84.2@120.85,36.725 v1(121.7,36.725)
  Signal Layer 4 w0.5: v1(100.125,60.65) 100.125,55.15 97.875,52.9 97.875,43.375 100.366,40.884 100.965,40.285 100.965,38.735 102.175,37.525 118,37.525 v1(118.65,36.875)
  Bottom Layer w0.4: v1(121.7,36.725) CN10.1@122.85,36.725
5V_VIN: C8.2 C86.2 C97.2 C120.2 C122.2 C123.2 C125.2 C130.2 C131.2 C134.2 C135.2 C162.1 C166.2 C167.2 CN8.2 CN8.4 D1.1 L12.1 Q1.5 Q1.6 R35.1 R152.2 R185.2 TP67.1 U19.11 U19.15 U19.21 U19.24 U19.25 U22.1 U22.6 U25.5 U25.6 U45.1 U45.6 | length 34.4
  Top Layer w0.2: v1(15.2,3.525) R185.2@15.2,4.275 ; TP67.1@17.125,10.375 17.138,10.362 17.138,8.913 U25.5@17.15,8.9 ; C131.2@35.45,25.825 36.175,25.825 36.8,25.2 U19.21@36.8,24.9 ; 35.65,23.4 U19.24@36.1,23.4 ; U19.25@36.1,23 34.959,23 ; U19.15@39.2,24.9 39.2,25.3 39.832,25.932 40.307,25.932 C120.2@40.325,25.95 ; L12.1@61.175,19.35 C135.2@61.175,20.6 C130.2@59.975,21.8 ; v1(80.875,63.9) R35.1@81.55,63.9 ; 34.959,23 34.55,23 34.364,23.186 34.364,23.536 v3(34.35,23.55) v3(33.75,23.55) 33.75,23.07 33.625,22.945 33.605,22.945 C134.2@33.825,22.725 34.125,22.425 34.125,22.375 34.334,22.375 34.959,23 ; C130.2@59.975,21.8 59.975,21.975 C130.2@59.775,22.175 59.775,22 C130.2@59.975,21.8
  Top Layer w0.25: C97.2@33.484,24.256 33.595,24.145 34.505,24.145 35.25,23.4 35.65,23.4
  Top Layer w0.3: v3(33.275,25.625) 33.275,24.736 33.379,24.633 33.379,24.386 C97.2@33.495,24.386 ; D1.1@99.245,62.575 v1(100.125,62.575) ; C86.2@101.675,36.1 102.425,35.35
  Top Layer w0.35: C122.2@9.35,23.275 9.425,23.2 U22.1@10.175,23.2 ; v1(19.05,23.2) U45.1@20.625,23.2
  Top Layer w0.4: v1(8.625,23.225) C122.2@9.35,23.225 ; v1@25.021,21.279 v1(25.05,21.25) ; C130.2@59.775,22 59.775,18.175 60.075,17.875 v1(60.075,17.025)
  Bottom Layer w0.2: R152.2@9.875,14.15 9.875,14.175 9.875,14.55 v1(10.525,15.2) ; CN8.4@44.16,92.23 44.16,90.24 C8.2@44.175,90.225 v1(44.175,89.575)
  other v1: 13.85,21.2 14.5,21.2 24.3,21.25 102.975,30.55 104.6,30.6
  other v3: 41.275,24.325 41.875,24.325 34.95,26.5 35.55,26.5 40.375,26.5 40.95,26.5
  other v5: 20.4,8.5 21,8.95 20.4,9.4 18.475,10 19.725,10 19.1,10.55
BOOT0: SW1.1 U14.Y17 | length 69.2
  Top Layer w0.075: U14.Y17@75.974,31.15 75.974,28.988 76.9,28.062 76.9,27.725
  Top Layer w0.1: v1(76.9,21.875) 76.9,27.725
  Signal Layer 2 w0.1: v1(35.075,18.975) 35.093,18.975 35.343,19.225 52.441,19.225 54.116,20.9 70.775,20.9 71.7,21.825 76.85,21.825 v1(76.9,21.875)
  Bottom Layer w0.1: v1(35.075,18.975) 35.075,16.15 37.286,13.939 37.761,13.939 39.075,12.625 39.075,6.09 SW1.1@40.3,4.865
BOOT1: SW1.2 U14.AA15 | length 66.6
  Top Layer w0.075: U14.AA15@74.975,30.65 74.975,29.471 75.115,29.331 75.115,28.285 75.675,27.725
  Top Layer w0.1: v1(75.025,22.275) 75.025,22.392 75.95,23.317 75.95,24.733 75.675,25.008 75.675,27.725
  Signal Layer 2 w0.1: v1(34.5,18.325) 34.5,19.025 34.9,19.425 52.358,19.425 54.258,21.325 54.825,21.325 70.858,21.325 71.808,22.275 v1(75.025,22.275)
  Bottom Layer w0.1: v1(34.5,18.325) 34.5,16.225 36.725,14 36.725,5.94 SW1.2@37.8,4.865
BOOT2: SW1.3 U14.Y15 | length 67.6
  Top Layer w0.075: U14.Y15@74.974,31.15 74.974,31.113 74.89,31.028 74.89,30.978 74.728,30.816 74.728,29.479 74.945,29.262 74.945,28.155 75.375,27.725
  Top Layer w0.1: v1(74.45,22.7) 74.895,22.7 75.12,22.925 75.201,22.925 75.45,23.174 ; 75.375,27.725 75.475,27.625 75.475,24.925 75.75,24.65 75.75,23.475 75.45,23.175
  Signal Layer 2 w0.1: v1@33.825,19 34.45,19.625 52.275,19.625 54.175,21.525 70.775,21.525 71.95,22.7 v1(74.45,22.7)
  Bottom Layer w0.1: v1(33.825,18.975) 33.825,18.325 34.275,17.875 34.275,15.8 34.575,15.5 ; 34.581,15.506 36.4,13.688 36.4,5.965 SW1.3@35.3,4.865
BT_DEV_WAKE: U1.39 U5.1 | length 47.8
  Top Layer w0.1: U5.1@71.475,79.425 72.6,79.425 v1(74.1,77.925) ; v1(107.575,88.675) U1.39@108.3,88.675
  Signal Layer 2 w0.1: v1(74.1,87.9) 74.175,87.825 106.725,87.825 v1(107.575,88.675)
  Bottom Layer w0.1: v1(74.1,77.925) v1(74.1,87.9)
BT_HOST_WAKE: R64.1 U1.38 | length 67.1
  Top Layer w0.1: R64.1@82.15,48.725 v1@90.65,48.725 ; v1(90.65,70.425) 90.772,70.425 90.872,70.325 108.716,70.325 108.73,70.339 108.914,70.339 v1(109,70.425) ; U1.38@108.3,88.225 v1(109,88.225)
  Bottom Layer w0.1: v1(90.65,70.425) 90.654,70.421 v1(90.654,48.777) ; v1(109,70.425) v1(109,88.225)
BT_PCM_CLK: TP11.1 U1.11 U14.E13 | length 80.3
  Top Layer w0.09: v2(73.975,38.15) U14.E13@73.975,38.65
  Top Layer w0.1: v1(81,47.425) 81.148,47.277 89.955,47.277 90.103,47.425 v1(91.2,47.425) ; v1(91.2,71.15) 97.774,71.15 97.824,71.2 98.176,71.2 98.226,71.15 v1(99.05,71.15) ; TP11.1@96.5,88.25 99.5,88.25 101.85,90.6 102.95,90.6 103.125,90.425 U1.11@103.125,90.025
  Bottom Layer w0.09: v2(73.975,38.15) 73.975,38.425 74.376,38.826 74.376,40.086 74.9,40.61 75.866,41.576 75.866,41.666 75.866,42.449 76.542,43.125
  Bottom Layer w0.1: 76.542,43.125 79.8,46.383 79.8,47 80.175,47.375 80.95,47.375 v1(81,47.425) ; v1(91.2,47.425) v1(91.2,71.15) ; v1(99.05,71.15) 99.05,81.899 99.075,81.924 99.075,82.276 99.05,82.301 v1(99.05,88.25)
BT_PCM_SDI: TP8.1 U1.10 U14.B13 | length 74.6
  Top Layer w0.075: 73.85,43.125 73.85,41.984 73.964,41.87 73.964,41.826 73.965,41.825 73.965,40.989 73.725,40.749 73.725,40.4 U14.B13@73.975,40.15
  Top Layer w0.1: 73.85,43.125 73.85,43.325 74.525,44 74.525,44.455 75.7,45.63 75.7,47.152 76.025,47.477 76.025,49.138 75.7,49.463 75.7,49.925 76.3,50.525 76.3,64.45 86.425,74.575 ; 86.426,74.575 86.675,74.824 ; 86.675,74.825 86.825,74.975 v1(100.075,74.975) ; TP8.1@99.5,89.75 100.625,90.875 103.175,90.875 103.575,90.475 U1.10@103.575,90.025
  Bottom Layer w0.1: v1(100.075,74.975) 100.15,75.05 v1(100.15,90.375)
BT_PCM_SDO: TP9.1 U1.9 U14.E14 | length 85.4
  Top Layer w0.09: v2@74.475,38.15 U14.E14@74.475,38.65
  Top Layer w0.1: v1(80.35,46.9) 90.075,46.9 v1@90.15,46.975 ; v1(90.15,71.65) v1(97.55,71.65) ; TP9.1@93.425,89.025 95.4,89.025 v1(97.55,91.175) 103.325,91.175 104.025,90.475 U1.9@104.025,90.025
  Bottom Layer w0.09: v2(74.475,38.225) 74.475,38.665 74.56,38.75 74.56,40.01 74.9,40.35 76.05,41.5 76.05,41.85 76.05,42.35 76.825,43.125
  Bottom Layer w0.1: 76.825,43.125 v1@80.35,46.65 ; v1@80.35,46.65 v1(80.35,46.9) ; v1(90.15,71.65) 90.204,71.596 v1(90.204,46.902) ; v1(97.55,71.65) v1(97.55,91.175)
BT_PCM_WS: TP1.1 U1.8 U14.D14 | length 85.1
  Top Layer w0.09: v2@74.075,39.15 U14.D14@74.475,39.15
  Top Layer w0.1: v1(80.4,47.8) 80.45,47.85 89.51,47.85 89.658,47.702 v1(89.779,47.702) ; v1(89.775,70.775) 90.399,70.775 90.474,70.85 90.863,70.85 90.988,70.725 91.376,70.725 91.426,70.775 v1(98,70.775) ; TP1.1@98.75,95.375 98.75,92.9 98,92.15 v1(98,91.8) 98.018,91.8 98.268,91.55 103.525,91.55 104.475,90.6 U1.8@104.475,90.025
  Bottom Layer w0.09: v2(74.025,39.225) 74.025,40 75.682,41.657 75.682,42.557 76.25,43.125
  Bottom Layer w0.1: 76.25,43.125 79.5,46.375 79.5,47.2 80.1,47.8 v1(80.4,47.8) ; v1(89.775,70.775) 89.779,70.771 v1(89.779,47.702) ; v1(98,70.775) v1(98,91.8)
BT_REG_ON: TP14.1 U1.14 U5.2 | length 35.9
  Top Layer w0.1: U5.2@71.475,80.075 74.675,80.075 76.575,81.975 78.625,81.975 83.825,87.175 97.05,87.175 97.575,87.7 99.825,87.7 100.138,87.388 ; TP14.1@99.5,86.75 100.138,87.388 ; U1.14@102.45,89.125 101.875,89.125 100.138,87.388
CAM_ENABLE: CN1.11 U5.20 U41.1 | length 56.4
  Top Layer w0.1: CN1.11@23.2,91.525 23.025,91.35 23.025,89.562 U41.1@22.975,89.512 22.988,89.5 v1(23.55,89.5) ; v1(64.555,80.075) U5.20@65.775,80.075
  Signal Layer 2 w0.1: v1(26.375,82.475) 26.375,83.55 26.6,83.775 55.849,83.775 55.899,83.725 64.675,83.725 v1(65.1,84.15)
  Bottom Layer w0.1: v1(23.55,89.5) 23.55,87.8 26.375,84.975 v1@26.375,82.525 ; v1(64.555,80.075) 64.555,83.605 v1(65.1,84.15)
CAM_RESET: CN1.12 U5.21 U40.1 | length 53.6
  Top Layer w0.1: CN1.12@24.2,91.525 24.2,90.125 24.325,90 24.325,89.55 U40.1@24.3,89.525 ; U40.1@24.325,89.538 v1(24.875,89.538) ; v1(54.9,87.55) 54.9,81.65 56.475,80.075 60.975,80.075 61.625,79.425 U5.21@65.775,79.425
  Signal Layer 2 w0.1: v1(26.025,86.15) 26.05,86.125 28.931,86.125 29.181,86.375 30.7,86.375 31.875,87.55 v1(54.9,87.55)
  Bottom Layer w0.1: v1(24.875,89.538) 24.875,87.3 v1(26.025,86.15)
CC1: CN12.A5 R147.2 R149.2 TP77.1 U44.1 | length 8.4
  Top Layer w0.2: CN12.A5@7.95,15.325 9.15,15.325 9.975,16.15 R147.2@10.55,16.15 U44.1@11.975,16.15 13.1,16.15 13.425,16.475 R149.2@14.5,16.475 TP77.1@14.5,17.8
CC2: CN12.B5 R144.2 R145.2 TP73.1 U44.2 | length 10
  Top Layer w0.2: CN12.B5@6.21,13.575 6.735,13.575 7.41,14.25 R145.2@10.55,14.25 13.125,14.25 13.45,13.925 R144.2@14.5,13.925 14.5,12.625 TP73.1@14.525,12.6
CLK_N: CN1.8 U2.E2 | length 28.8
  Top Layer w0.09: CN1.8@20.2,91.525 v1(20.2,92.8)
  Signal Layer 1 w0.075: v4(32.375,89.35) 32.346,89.379 32.346,89.514 32.09,89.77 32.09,91.45 32.356,91.717 32.356,92.731 v1(32.376,92.751)
  Bottom Layer w0.09: v1(20.2,92.8) 20.283,92.8 20.483,93 21.725,93 21.925,93.2 21.943,93.2 22.297,93.2 22.395,93.103 22.395,91.975 22.644,91.725 23.055,91.725 23.305,91.975 23.305,93.144 23.402,93.242 23.597,93.242 23.695,93.144 23.695,91.975 23.944,91.725 24.355,91.725 24.605,91.975 24.605,93.103 24.702,93.2 24.823,93.2 27.475,93.2 28.467,93.2 28.717,93.45 28.717,93.761 28.814,93.859 29.009,93.859 29.107,93.761 29.107,92.631 29.356,92.381 29.767,92.381 30.017,92.631 30.017,93.761 30.114,93.859 30.309,93.859 30.407,93.761 30.407,92.631 30.656,92.381 31.067,92.381 31.317,92.631 31.317,93.103 31.414,93.2 31.535,93.2 32.872,93.2 32.925,93.147 32.925,92.825 32.859,92.759 32.384,92.759 v1(32.376,92.751)
CLK_P: CN1.9 U2.D1 | length 27.9
  Top Layer w0.09: CN1.9@21.2,91.525 21.2,93.15 v1(21.475,93.425)
  Signal Layer 1 w0.075: v4(32.775,89.75) 32.746,89.779 32.611,89.779 32.465,89.925 32.465,91.295 32.731,91.561 32.731,92.131 v1(32.775,92.175)
  Bottom Layer w0.09: v1(21.475,93.425) 21.51,93.46 21.943,93.46 22.405,93.46 22.655,93.21 22.655,92.082 22.752,91.985 22.947,91.985 23.045,92.082 23.045,93.252 23.294,93.502 23.705,93.502 23.955,93.252 23.955,92.082 24.052,91.985 24.247,91.985 24.345,92.082 24.345,93.21 24.594,93.46 24.823,93.46 27.475,93.46 28.359,93.46 28.457,93.557 28.457,93.869 28.706,94.119 29.117,94.119 29.367,93.869 29.367,92.738 29.464,92.641 29.659,92.641 29.757,92.738 29.757,93.869 30.006,94.119 30.417,94.119 30.667,93.869 30.667,92.738 30.764,92.641 30.959,92.641 31.057,92.738 31.057,93.21 31.306,93.46 31.535,93.46 32.98,93.46 33.185,93.255 33.185,92.585 v1(32.775,92.175)
DATA1_N: CN1.2 U2.F1 | length 28.4
  Top Layer w0.09: CN1.2@14.2,91.525 14.2,92.15 14.455,92.405 14.517,92.405 14.57,92.458 14.57,93.405 v1(14.2,93.775) ; v1(31.75,95.875) 31.75,95.704 31.8,95.654 31.225,95.079 31.225,92.673 32.52,91.378 32.52,90.688 32.04,90.208 32.04,89.99 31.985,89.935 31.985,89.76 U2.F1@31.975,89.75
  Bottom Layer w0.09: v1(14.2,93.775) 14.57,94.145 14.57,94.563 15.642,95.635 17.467,95.635 31.485,95.635 31.725,95.875 v1(31.75,95.875)
DATA1_P: CN1.3 U2.E1 | length 27.8
  Top Layer w0.09: CN1.3@15.2,91.525 15.2,92.15 14.945,92.405 14.883,92.405 14.83,92.458 14.83,93.405 v1(15.2,93.775) ; v1(32.1,95.3) 31.814,95.3 31.485,94.971 31.485,92.781 32.78,91.486 32.78,90.58 32.3,90.1 32.3,90.02 32.375,89.945 U2.E1@32.375,89.75
  Bottom Layer w0.09: v1(15.2,93.775) 14.83,94.145 14.83,94.455 15.75,95.375 17.575,95.375 32.025,95.375 v1(32.1,95.3)
DATA2_N: CN1.5 U2.D2 | length 29.2
  Top Layer w0.09: CN1.5@17.2,91.525 17.377,91.702 17.377,92.532 17.595,92.75 17.595,93.63 v1(17.225,94) ; v1(32.825,95.15) 32.825,94.929 32.55,94.654 32.55,93.775 32.55,93.342 33.265,92.627 v4@33.265,91.2
  Signal Layer 1 w0.075: v4(32.775,89.35) 32.825,89.35 32.9,89.425 33.315,89.425 33.849,89.959 33.849,90.621 33.415,91.055 33.27,91.2 v4(33.26,91.2)
  Bottom Layer w0.09: v1(17.225,94) 17.595,94.37 17.595,94.558 17.872,94.835 21.845,94.835 22.724,94.835 22.974,94.585 22.974,94.367 23.071,94.27 23.266,94.27 23.364,94.367 23.364,94.609 23.613,94.859 24.024,94.859 24.274,94.609 24.274,94.367 24.371,94.27 24.566,94.27 24.664,94.367 24.664,94.609 24.913,94.859 25.324,94.859 25.574,94.609 25.574,94.367 25.671,94.27 25.866,94.27 25.964,94.367 25.964,94.609 26.213,94.859 26.624,94.859 26.874,94.609 26.874,94.367 26.971,94.27 27.166,94.27 27.264,94.367 27.264,94.585 27.513,94.835 28.557,94.835 32.51,94.835 v1(32.825,95.15)
DATA2_P: CN1.6 U2.C1 | length 27.8
  Top Layer w0.09: CN1.6@18.2,91.525 18.073,91.652 18.073,92.532 17.855,92.75 17.855,93.63 v1(18.225,94) ; v4(33.26,90.68) 33.535,90.955 33.535,91.314 33.525,91.324 33.525,92.735 32.81,93.45 32.81,94.546 32.889,94.625 33.225,94.625 v1(33.275,94.575)
  Signal Layer 1 w0.075: v4(33.175,89.75) 33.474,90.049 33.474,90.466 v4(33.26,90.68)
  Bottom Layer w0.09: v1(18.225,94) 17.855,94.37 17.855,94.45 17.98,94.575 21.845,94.575 22.616,94.575 22.714,94.478 22.714,94.26 22.963,94.01 23.374,94.01 23.624,94.26 23.624,94.502 23.721,94.599 23.916,94.599 24.014,94.502 24.014,94.26 24.263,94.01 24.674,94.01 24.924,94.26 24.924,94.502 25.021,94.599 25.216,94.599 25.314,94.502 25.314,94.26 25.563,94.01 25.974,94.01 26.224,94.26 26.224,94.502 26.321,94.599 26.516,94.599 26.614,94.502 26.614,94.26 26.863,94.01 27.274,94.01 27.524,94.26 27.524,94.478 27.621,94.575 28.557,94.575 v1(33.275,94.575)
DCMI_D0: TP32.1 U4.13 U14.A2 | length 97.4
  Top Layer w0.075: 67.475,43.125 67.475,42.388 68.475,41.388 U14.A2@68.475,40.65
  Top Layer w0.1: TP32.1@9.5,79.45 13.975,79.45 14.575,80.05 U4.13@19.65,80.05 20.624,80.05 20.649,80.025 21.75,80.025 22.775,79 22.775,72.325 22.5,72.05 v1(22.5,69.225) ; v1(66.775,69.225) 66.725,69.175 66.725,56.276 66.775,56.226 66.775,49.4 67.478,48.697 67.478,43.26 67.475,43.257 67.475,43.125
  Signal Layer 2 w0.219: v1(22.5,69.225) v1(66.775,69.225)
DCMI_D1: U4.14 U14.B1 | length 87.4
  Top Layer w0.075: 66.55,43.125 66.65,43.025 66.65,41.05 67.55,40.15 U14.B1@67.975,40.15
  Top Layer w0.1: U4.14@19.65,79.65 21.55,79.65 22.5,78.7 22.5,72.5 21.825,71.825 v1(21.825,69.775) ; v1(65.525,69.775) 65.525,69.025 65.45,68.95 65.45,49.575 65.125,49.25 65.125,44.55 66.55,43.125
  Signal Layer 2 w0.219: v1(21.825,69.775) v1(65.525,69.775)
DCMI_D2: U4.16 U14.G2 | length 86.2
  Top Layer w0.075: 65.175,38.917 66.647,37.445 67.769,37.445 67.811,37.404 68.079,37.404 68.314,37.639 68.464,37.639 U14.G2@68.475,37.65
  Top Layer w0.1: U4.16@19.65,78.85 20.975,78.85 22.275,77.55 22.275,73.45 v1@21.825,73 ; v1(56.675,72.975) 56.675,54.95 57.975,53.65 57.975,50.625 59.4,49.2 59.4,41.475 61.2,39.675 64.417,39.675 65.175,38.917
  Signal Layer 2 w0.219: v1(21.825,72.975) v1(56.675,72.975)
DCMI_D3: U4.17 U14.H2 | length 85.6
  Top Layer w0.075: 65.175,38.325 66.393,37.107 67.629,37.107 67.671,37.066 68.353,37.066 68.438,37.15 U14.H2@68.475,37.15
  Top Layer w0.1: U4.17@19.65,78.45 20.65,78.45 21.825,77.275 v1(21.825,74) v1@21.825,73.975 ; v1(55.8,74) 55.8,67.899 55.85,67.849 55.85,54.7 57.25,53.3 57.25,49.424 57.45,49.224 57.45,42.5 60.775,39.175 64.325,39.175 65.175,38.325
  Signal Layer 2 w0.219: v1(21.825,74) 34.268,74 34.418,73.85 38.375,73.85 38.525,74 v1(55.8,74)
DCMI_D4: U4.19 U14.F3 | length 84.6
  Top Layer w0.075: 65.175,42.124 65.29,42.009 65.29,40.01 66.903,38.397 68.578,38.397 68.814,38.161 68.964,38.161 U14.F3@68.975,38.15
  Top Layer w0.1: U4.19@19.65,77.65 20.65,77.65 21.4,76.9 v1@21.4,72.425 ; v1(60.7,72.35) 60.65,72.3 60.65,52.7 62.3,51.05 62.3,44.992 65.092,42.2 65.099,42.2 65.175,42.124
  Signal Layer 2 w0.219: v1(21.425,72.35) v1(60.7,72.35)
DCMI_D5: U4.20 U14.C2 | length 85.3
  Top Layer w0.075: 65.625,43.125 66.14,42.61 66.14,40.585 67.325,39.4 68.225,39.4 U14.C2@68.475,39.65
  Top Layer w0.1: U4.20@19.65,77.25 20.6,77.25 21.15,76.7 21.15,74.575 20.95,74.375 v1(20.95,70.275) ; v1(63.575,70.275) 64.4,69.45 64.4,64.125 63.575,63.3 63.575,61.001 63.5,60.926 63.5,54.125 64.325,53.3 64.325,44.425 65.625,43.125
  Signal Layer 2 w0.219: v1(20.95,70.275) v1(63.575,70.275)
DCMI_D6: U4.22 U14.D1 | length 84.5
  Top Layer w0.075: 65.325,43.125 65.97,42.48 65.97,40.43 67.25,39.15 U14.D1@67.975,39.15
  Top Layer w0.1: U4.22@19.65,76.45 20.625,76.45 20.9,76.175 20.9,74.725 20.475,74.3 v1(20.475,71.3) ; v1(63.2,71.3) 63.25,71.25 63.25,70.551 63.15,70.451 63.15,69.743 64.075,68.818 64.075,64.327 63.25,63.502 63.25,53 64.05,52.2 64.05,44.4 65.325,43.125
  Signal Layer 2 w0.219: v1(20.475,71.3) v1(63.2,71.3)
DCMI_D7: U4.23 U14.C3 | length 85.7
  Top Layer w0.075: 66.267,43.125 66.48,42.912 66.48,40.845 67.425,39.9 68.725,39.9 U14.C3@68.975,39.65
  Top Layer w0.1: U4.23@19.65,76.05 20.475,76.05 20.625,75.9 20.625,74.825 19.925,74.125 v1(19.925,70.8) ; v1(65.175,70.8) 64.8,70.425 64.8,69.7 65.175,69.325 65.175,49.583 64.925,49.333 64.925,44.467 66.267,43.125
  Signal Layer 2 w0.219: v1(19.925,70.8) v1(65.175,70.8)
DCMI_HSYNC: TP21.1 U4.5 U14.E3 | length 97.8
  Top Layer w0.075: 65.175,42.7 65.63,42.245 65.63,40.22 67.115,38.735 68.15,38.735 68.315,38.9 68.725,38.9 U14.E3@68.975,38.65
  Top Layer w0.1: TP21.1@12,83.95 12.55,83.4 18.1,83.4 18.275,83.225 19.625,83.225 U4.5@19.65,83.25 21.05,83.25 21.425,82.875 21.425,80.875 23.025,79.275 v1(23.025,71.825) ; v1(61.9,71.825) 61.95,71.775 61.95,53.875 62.375,53.45 62.375,52.675 63.575,51.475 63.575,44.3 65.175,42.7
  Signal Layer 2 w0.219: v1(23.025,71.825) v1(61.9,71.825)
DCMI_PIXCLK: TP13.1 U4.2 U14.C6 | length 106.6
  Top Layer w0.075: 69.9,43.125 69.9,42.875 70.059,42.716 70.059,40.414 70.221,40.252 70.221,40.229 70.225,40.225 70.225,39.9 U14.C6@70.475,39.65
  Top Layer w0.1: TP13.1@12,86.95 14.3,86.95 16.8,84.45 U4.2@19.65,84.45 20.9,84.45 22,83.35 22,81.225 23.575,79.65 23.575,74.45 24.025,74 24.025,73.2 23.575,72.75 23.575,69.55 22.7,68.675 v1(21.925,68.675) ; v1(69.475,69.125) 69.075,68.725 69.075,60.347 69.503,59.919 69.503,59.527 69.475,59.499 69.475,48.15 69.1,47.775 69.1,45.675 69.425,45.35 69.425,43.75 69.9,43.275 69.9,43.125
  Signal Layer 2 w0.219: v1(21.925,68.675) 66.943,68.675 67.393,69.125 v1(69.475,69.125)
DCMI_VSYNC: TP17.1 U4.3 U14.F2 | length 101.3
  Top Layer w0.075: 65.175,39.483 65.579,39.079 65.579,39.071 66.75,37.9 68.225,37.9 U14.F2@68.475,38.15
  Top Layer w0.1: TP17.1@9.5,85.45 14.675,85.45 15.925,84.2 18.75,84.2 18.9,84.05 U4.3@19.65,84.05 20.775,84.05 21.7,83.125 21.7,81.05 23.275,79.475 23.275,74.375 23.55,74.1 v1(23.55,73.475) ; v1(60.325,73.475) 60.35,73.45 60.35,72.601 60.275,72.526 60.275,72.174 60.35,72.099 60.35,52.425 61.95,50.825 61.95,45 62.875,44.075 62.875,41.802 62.83,41.757 62.83,40.414 62.919,40.325 64.333,40.325 65.175,39.483
  Signal Layer 2 w0.219: v1(23.55,73.475) v1(60.325,73.475)
DDR_A0: U14.H20 U17.N3 | length 30.1
  Top Layer w0.075: U14.H20@77.47,37.145 77.643,37.145 77.719,37.069 77.729,37.069 77.733,37.066 78.217,37.066 78.22,37.069 78.315,37.163 79.129,37.163 79.233,37.06 v2@79.59,37.06
  Top Layer w0.09: U17.N3@87.945,35.695 v2(88.35,36.1)
  Bottom Layer w0.09: v2@79.662,37 80.032,37.37 80.558,37.37 80.83,37.642 80.83,38.1 80.938,38.208 80.938,38.633 80.69,38.88 80.69,39.26 80.95,39.52 80.95,39.788 80.675,40.063 80.675,40.25 80.938,40.513 80.938,41.637 80.6,41.975 80.6,42.15 81.25,42.8 86.405,42.8 86.702,42.502 86.702,42.252 86.415,41.965 86.415,41.56 86.725,41.25 86.725,41.02 86.465,40.76 85.732,40.76 85.087,40.115 84.595,40.115 82.93,38.45 82.93,37.098 84.148,35.88 84.916,35.88 85.257,35.54 87.79,35.54 v2(88.35,36.1) v2@88.375,36.125
  other v2: 79.675,37.025
DDR_A1: U14.N21 U17.P7 | length 29.9
  Top Layer w0.075: U14.N21@77.975,34.65 78.013,34.65 78.093,34.73 78.892,34.73 79.467,34.155 v2@80.755,34.155
  Top Layer w0.09: v2(86.75,32.025) 87.15,32.425 U17.P7@87.15,32.5
  Bottom Layer w0.09: v2(80.7,34.175) 80.7,34.173 81.285,33.588 81.285,33.1 81.535,32.85 81.535,26.379 81.657,26.257 81.738,26.257 82.057,25.938 82.057,25.857 82.195,25.719 84.828,25.719 85.009,25.9 85.175,25.9 85.356,25.719 85.593,25.719 85.725,25.851 85.725,25.975 85.454,26.246 85.454,26.346 85.784,26.675 85.925,26.675 86.075,26.525 86.275,26.525 86.35,26.6 86.35,27.2 86.275,27.275 85.75,27.275 85.62,27.405 85.62,27.595 85.7,27.675 86.15,27.675 86.219,27.744 86.219,27.919 86.117,28.02 85.377,28.02 84.698,28.698 84.598,28.698 84.525,28.625 84.525,28.545 84.425,28.445 84.295,28.445 84.19,28.55 84.19,31.395 84.3,31.505 84.3,31.6 84.19,31.71 84.19,31.85 84.425,32.085 84.7,32.085 84.85,31.935 85.21,31.935 85.36,32.085 85.565,32.085 85.625,32.025 85.625,31.81 85.695,31.74 86.21,31.74 86.26,31.79 86.26,31.95 86.335,32.025 v2(86.75,32.025)
DDR_A2: U14.G20 U17.P3 | length 30.3
  Top Layer w0.075: U14.G20@77.47,37.645 77.48,37.635 77.634,37.635 77.861,37.407 77.869,37.407 77.873,37.404 78.077,37.404 78.176,37.503 79.366,37.503 79.535,37.672 79.722,37.672 v2(79.775,37.725)
  Top Layer w0.09: U17.P3@87.145,35.695 v2(87.55,36.1)
  Bottom Layer w0.09: v2(79.775,37.725) 79.875,37.625 80.388,37.625 80.595,37.832 80.595,38.565 80.25,38.91 80.25,39.23 80.575,39.555 80.575,39.67 80.195,40.05 80.195,40.245 80.5,40.55 80.5,40.7 80.195,41.005 80.195,41.12 80.475,41.4 80.475,41.62 80.195,41.9 80.195,42.185 81.13,43.12 86.495,43.12 87.15,42.465 87.15,42.29 86.705,41.845 86.705,41.68 86.81,41.575 87.125,41.575 87.26,41.44 87.26,41.145 86.585,40.47 85.852,40.47 85.207,39.825 84.715,39.825 83.22,38.33 83.22,37.19 84.24,36.17 85.036,36.17 85.377,35.83 87.347,35.83 87.4,35.882 87.4,35.892 87.55,36.042 v2(87.55,36.1)
DDR_A3: U14.H19 U17.N2 | length 30.8
  Top Layer w0.075: U14.H19@76.97,37.145 77.224,37.399 77.629,37.399 77.79,37.238 77.799,37.238 77.803,37.235 78.147,37.235 78.245,37.333 79.45,37.333 79.497,37.38 80.105,37.38 80.25,37.525 v2(80.25,37.975)
  Top Layer w0.09: U17.N2@87.945,36.495 v2(88.35,36.9)
  Bottom Layer w0.09: v2(80.25,37.975) 80.25,38.5 79.905,38.845 79.905,42.305 81.01,43.41 86.615,43.41 87.55,42.475 87.55,41.025 86.705,40.18 85.972,40.18 85.327,39.535 84.835,39.535 83.51,38.21 83.51,37.282 84.332,36.46 85.156,36.46 85.492,36.125 87.025,36.125 87.4,36.5 87.95,36.5 v2(88.35,36.9)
